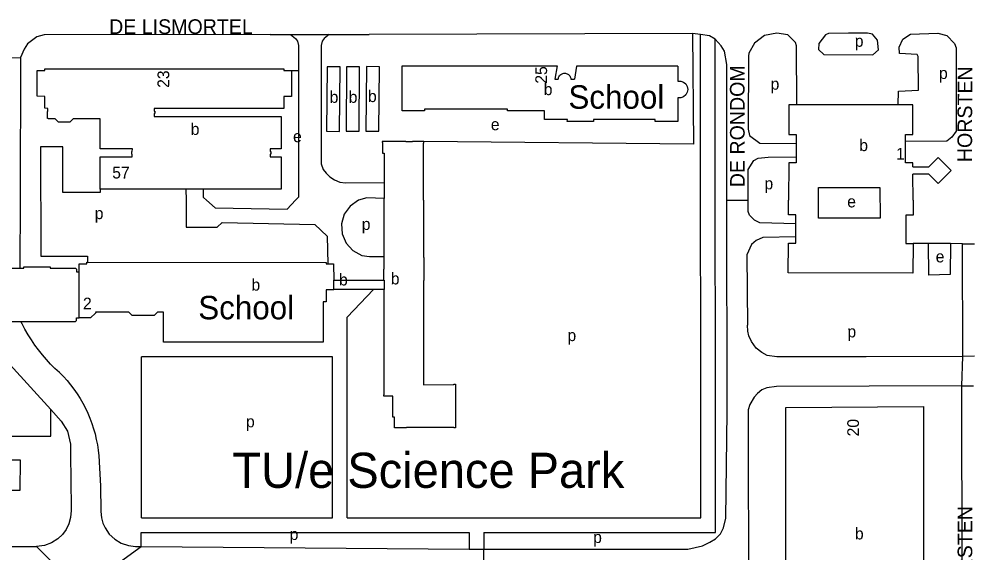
# Model space of a CAD drawing. Extents: x 161494 to 163033, y 383688 to 384862.
# Drawn here: x 162191.5 to 162517.1, y 384379.7 to 384561.8 of the extents above; entities that cross this region are included whole.
import ezdxf

# ---------------------------------------------------------------- set-up
doc = ezdxf.new("R2010")
doc.units = 0
for name, color, linetype in [('BLT_Basislijn', 7, 'Continuous'), ('BLT_Bebouwing', 7, 'Continuous'), ('BLT_Bebouwing_beschrifting', 7, 'Continuous'), ('BLT_Centroide', 7, 'Continuous'), ('BLT_Huisnummer', 7, 'Continuous'), ('BLT_Huisnummer_reeks', 7, 'Continuous'), ('BLT_Onderdoorgang_en_onderverdeling', 7, 'Continuous'), ('BLT_Onderverdeling_panden', 7, 'Continuous'), ('BLT_Sport_parknaam', 7, 'Continuous'), ('BLT_Straatnaam', 7, 'Continuous'), ('BLT_Vlakafsluiter', 7, 'Continuous')]:
    doc.layers.add(name, color=color, linetype=linetype)

msp = doc.modelspace()

# ---------------------------------------------------------------- linework, layer by layer
at = {"layer": 'BLT_Basislijn'}
for p, q in [((162277.25, 384556.55), (162284.21, 384556.56)), ((162284.21, 384556.56), (162291.93, 384556.57)), ((162291.93, 384556.57), (162297.41, 384556.57)), ((162297.41, 384556.57), (162311.03, 384556.59)), ((162421.44, 384556.93), (162311.03, 384556.59)), ((162424.11, 384556.57), (162421.44, 384556.93)), ((162424.22, 384391.71), (162424.11, 384556.57)), ((162429.23, 384386.71), (162429.11, 384555.03)), ((162284.55, 384544.31), (162286.93, 384544.24)), ((162286.93, 384544.24), (162286.93, 384501.09)), ((162248.5, 384503.76), (162248.51, 384500)), ((162286.93, 384501.09), (162285.92, 384500)), ((162191.85, 384500), (162191.79, 384476.84)), ((162258.48, 384497.41), (162255.56, 384500)), ((162285.92, 384500), (162283.04, 384496.92)), ((162258.48, 384497.41), (162283.04, 384496.92)), ((162260.8, 384492.37), (162292.53, 384491.73)), ((162292.53, 384491.73), (162296.74, 384487.8)), ((162296.74, 384487.8), (162296.91, 384478.32)), ((162513.58, 384485.17), (162517.59, 384485.2)), ((162303.54, 384391.71), (162303.54, 384460.12)), ((162233.3, 384391.71), (162233.3, 384446.58)), ((162298.54, 384391.71), (162298.54, 384446.55)), ((162517.68, 384446.82), (162513.64, 384446.73)), ((162188.54, 384443.92), (162202.39, 384428.59)), ((162513.36, 384436.68), (162517.26, 384436.66)), ((162513.52, 384355.52), (162513.36, 384436.68)), ((162350.2, 384391.71), (162424.22, 384391.71)), ((162233.21, 384381.92), (162233.17, 384386.71)), ((162350.2, 384386.71), (162429.23, 384386.71)), ((162127.04, 384381.9), (162197.47, 384381.94)), ((162233.21, 384381.92), (162345.2, 384381))]:
    msp.add_line(p, q, dxfattribs=at)
for points in [[(162277.25, 384556.55), (162200.08, 384556.42), (162197.64, 384555.73), (162194.42, 384553.41), (162193.24, 384551.6), (162191.97, 384548.7)], [(162284.21, 384556.56), (162285.91, 384555.21), (162286.61, 384554.27), (162286.93, 384552.82), (162286.93, 384544.24)], [(162297.41, 384556.57), (162295.7, 384555.21), (162295, 384554.27), (162294.67, 384552.82), (162294.67, 384512.49), (162295.34, 384510.54), (162296.33, 384509.26), (162297.6, 384508.03), (162299.2, 384507), (162301.03, 384506.24), (162302.96, 384505.97), (162316.16, 384506.06)], [(162421.44, 384556.93), (162421.79, 384519.13), (162329.71, 384520.04)], [(162429.11, 384555.03), (162427.14, 384556.15), (162424.11, 384556.57)], [(162457.04, 384532.57), (162456.89, 384552.68), (162456.58, 384553.79), (162453.97, 384556.49), (162450.15, 384556.97), (162445.98, 384556.21), (162442.58, 384553.63), (162440.67, 384550.23), (162440.48, 384549.23), (162440.36, 384524.31), (162440.83, 384522.15), (162444.39, 384519.47), (162456.75, 384519.33)], [(162474.63, 384556.98), (162467.77, 384556.94), (162466.82, 384556.43), (162464.52, 384553.47), (162464.37, 384551.5), (162466.27, 384549.77), (162482.91, 384549.62), (162484.88, 384551.34), (162484.56, 384554.59), (162482.81, 384556.65), (162481.14, 384557), (162474.63, 384556.98)], [(162491.59, 384532.57), (162491.76, 384537.21), (162498.52, 384537.53), (162498.38, 384549.07), (162498.11, 384549.78), (162492.04, 384550.13), (162491.92, 384552.2), (162493.15, 384555), (162495.79, 384556.7), (162505.17, 384557.05), (162508.16, 384556.18), (162510.8, 384553.47), (162511.43, 384552.04), (162511.43, 384523.64), (162509.96, 384521.5), (162508.26, 384520.17), (162494.14, 384520.08)], [(162433.15, 384500), (162433.12, 384546.37), (162432.31, 384550.83), (162431.16, 384552.66), (162429.11, 384555.03)], [(162191.97, 384548.7), (162191.85, 384500)], [(162219.25, 384503.76), (162219.25, 384502.68), (162206.47, 384502.68), (162206.46, 384518.29), (162198.88, 384518.28), (162198.99, 384480.93), (162214.88, 384480.93), (162214.9, 384478.86)], [(162440.4, 384500), (162440.39, 384510.51), (162442.33, 384513.56), (162443.76, 384514.39), (162447.27, 384514.72), (162456.75, 384514.87)], [(162255.56, 384500), (162254.48, 384500.95), (162254.48, 384503.76)], [(162316.16, 384500.57), (162310.19, 384500.88), (162307.36, 384500), (162304.53, 384498.05), (162302.48, 384495.28), (162301.63, 384491.95), (162301.76, 384488.51), (162303.13, 384485.36), (162305.47, 384482.82), (162308.5, 384481.21), (162311.16, 384480.85), (162316.17, 384480.8)], [(162248.51, 384500), (162248.53, 384490.85), (162259.19, 384490.85), (162260.8, 384492.37)], [(162433.2, 384427.7), (162433.15, 384500)], [(162456.64, 384492), (162444.33, 384492.3), (162442.52, 384493.27), (162440.83, 384494.95), (162440.4, 384496.16), (162440.4, 384500)], [(162456.63, 384487.55), (162445.43, 384487.33), (162443.12, 384486.24), (162441.53, 384484.94), (162439.99, 384481.37), (162440.17, 384457.38)], [(162501.89, 384485.28), (162496.67, 384485.22)], [(162509.43, 384485.25), (162509.32, 384474.63), (162502.05, 384474.44), (162501.89, 384485.28)], [(162509.43, 384485.25), (162501.89, 384485.28)], [(162513.58, 384485.17), (162509.43, 384485.25)], [(162513.64, 384446.73), (162513.58, 384485.17)], [(162312.55, 384469.57), (162303.54, 384460.12)], [(162205.33, 384441.23), (162203.78, 384442.66), (162202.29, 384444.14), (162200.85, 384445.68), (162199.48, 384447.28), (162198.16, 384448.93), (162196.91, 384450.62), (162195.72, 384452.36), (162194.6, 384454.15), (162193.55, 384455.98), (162192.57, 384457.84), (162192.18, 384458.64)], [(162513.64, 384446.73), (162480.72, 384446.63), (162450.17, 384446.55), (162446.93, 384447.01), (162445.01, 384448.02), (162443.12, 384449.56), (162441.53, 384451.77), (162440.66, 384453.71), (162440.27, 384455.38), (162440.17, 384457.38)], [(162298.54, 384446.55), (162233.3, 384446.58)], [(162205.33, 384441.23), (162206.66, 384439.89), (162207.93, 384438.49), (162209.14, 384437.04), (162210.28, 384435.54), (162211.36, 384433.99), (162212.38, 384432.4), (162213.32, 384430.77), (162214.2, 384429.1), (162215, 384427.39), (162215.73, 384425.65), (162216.39, 384423.88), (162216.97, 384422.08), (162217.48, 384420.27), (162217.9, 384418.43), (162218.25, 384416.57), (162218.52, 384414.71), (162218.71, 384412.83), (162218.82, 384410.94), (162218.83, 384410.7)], [(162513.36, 384436.68), (162450.09, 384436.43), (162446.77, 384436.05), (162445.01, 384435.32), (162443.54, 384434.13), (162442.46, 384432.84), (162440.96, 384430.36), (162440.4, 384428.46), (162440.34, 384425.23), (162440.51, 384363.61)], [(162121.02, 384419.5), (162202.39, 384419.51), (162202.39, 384428.59)], [(162202.39, 384428.59), (162205.94, 384424.66), (162208.03, 384421.25), (162209.1, 384416.8), (162209.1, 384409.79), (162209.2, 384407.98), (162209.21, 384406.16), (162209.19, 384405.28), (162209.34, 384394.14), (162209.14, 384391.74), (162208.53, 384389.57), (162207.62, 384387.72), (162206.31, 384385.95), (162204.76, 384384.5), (162202.6, 384383.15), (162200.19, 384382.28), (162197.47, 384381.94)], [(162350.2, 384381), (162418.98, 384380.95), (162419.84, 384380.99), (162424.82, 384382.11), (162427.33, 384383.31), (162429.21, 384384.54), (162430.9, 384386.23), (162431.97, 384388.21), (162432.76, 384391.57), (162433.2, 384427.7)], [(162218.83, 384410.7), (162219.36, 384402.56), (162219.4, 384393.87), (162219.63, 384391.67), (162220.14, 384389.87), (162220.89, 384388.2), (162222.33, 384386.1), (162224.18, 384384.34), (162226.43, 384382.98), (162228.93, 384382.19), (162231.24, 384381.92), (162233.21, 384381.92)], [(162233.3, 384391.71), (162298.54, 384391.71)], [(162303.54, 384391.71), (162350.2, 384391.71)], [(162233.17, 384386.71), (162345.2, 384386.71)], [(162345.2, 384386.71), (162345.2, 384381)], [(162350.2, 384386.71), (162350.2, 384381)], [(162345.2, 384381), (162350.2, 384381)]]:
    msp.add_lwpolyline(points, dxfattribs=at)
at = {"layer": 'BLT_Bebouwing'}
for p, q in [((162322.28, 384545.89), (162375.17, 384545.88)), ((162491.59, 384532.57), (162457.04, 384532.57)), ((162456.75, 384519.33), (162456.75, 384514.87)), ((162496.73, 384500), (162496.62, 384508.92)), ((162316.16, 384506.06), (162316.16, 384500.57)), ((162254.48, 384503.76), (162248.5, 384503.76)), ((162456.63, 384487.55), (162456.64, 384492)), ((162212.09, 384475.58), (162212.09, 384478.35)), ((162212.09, 384478.35), (162212.46, 384478.35)), ((162182.42, 384476.83), (162191.79, 384476.84)), ((162304.77, 384472.76), (162316.02, 384472.77)), ((162181.72, 384458.64), (162192.18, 384458.64))]:
    msp.add_line(p, q, dxfattribs=at)
for points in [[(162197.68, 384535.47), (162197.71, 384544.33), (162200.32, 384544.32), (162200.32, 384544.87), (162281.95, 384544.82), (162281.95, 384544.32), (162284.55, 384544.31)], [(162284.55, 384544.31), (162284.56, 384535.44), (162281.95, 384535.43), (162281.95, 384531.34), (162237.64, 384531.34), (162237.65, 384530.43), (162237.85, 384530.43), (162237.85, 384529.56), (162237.65, 384529.56), (162237.65, 384528.64), (162264.6, 384528.62), (162280.98, 384528.62), (162280.96, 384517.54), (162277.24, 384517.55), (162277.23, 384516.64), (162277.43, 384516.64), (162277.43, 384515.77), (162277.23, 384515.77), (162277.23, 384514.84), (162280.94, 384514.83), (162280.94, 384503.75), (162254.48, 384503.76)], [(162416.35, 384545.74), (162416.35, 384540.66), (162417.36, 384540.66), (162418.31, 384540.32), (162419.07, 384539.68), (162419.57, 384538.82), (162419.75, 384537.84), (162419.57, 384536.85), (162419.08, 384535.98), (162418.31, 384535.34), (162417.38, 384534.98), (162416.37, 384534.96), (162416.38, 384526.89), (162408.67, 384526.89), (162408.67, 384527.54), (162387.58, 384527.54), (162387.58, 384526.89), (162378.66, 384526.9), (162378.76, 384527.54), (162370.87, 384527.56), (162370.88, 384530.49), (162358.27, 384530.49), (162358.27, 384531.14), (162329.97, 384531.14), (162329.97, 384530.49), (162322.27, 384530.5), (162322.28, 384545.89)], [(162375.17, 384545.88), (162374.39, 384541.29), (162375.59, 384541.28), (162375.62, 384541.58), (162375.68, 384541.85), (162375.81, 384542.16), (162375.95, 384542.42), (162376.16, 384542.67), (162376.41, 384542.9), (162376.66, 384543.07), (162376.92, 384543.2), (162377.18, 384543.29), (162377.47, 384543.34), (162377.78, 384543.36), (162378.05, 384543.34), (162378.31, 384543.27), (162378.56, 384543.19), (162378.79, 384543.07), (162379.03, 384542.92), (162379.27, 384542.7), (162379.49, 384542.44), (162379.66, 384542.16), (162379.75, 384541.93), (162379.82, 384541.67), (162379.86, 384541.46), (162379.87, 384541.3), (162381.09, 384541.3)], [(162416.35, 384545.74), (162381.84, 384545.72), (162381.09, 384541.3)], [(162219.25, 384503.76), (162219.26, 384514.84), (162230.18, 384514.84), (162230.19, 384515.78), (162229.99, 384515.78), (162229.99, 384516.64), (162230.19, 384516.64), (162230.21, 384517.56), (162219.26, 384517.56), (162219.26, 384527.84), (162210.05, 384527.85), (162208.9, 384526.69), (162208.77, 384526.64), (162205.1, 384526.64), (162204.96, 384526.69), (162203.83, 384527.84), (162201.51, 384527.84), (162201.51, 384527.87), (162201.28, 384527.87), (162201.27, 384527.96), (162201.24, 384527.96), (162201.25, 384530.33), (162201.37, 384530.33), (162201.37, 384531.37), (162200.28, 384531.38), (162200.3, 384535.46), (162197.68, 384535.47)], [(162457.04, 384532.57), (162454.27, 384532.57), (162454.26, 384522.46), (162456.74, 384522.46), (162456.75, 384519.33)], [(162494.14, 384520.08), (162494.14, 384522.47), (162496.62, 384522.46), (162496.63, 384532.57), (162491.59, 384532.57)], [(162329.71, 384520.04), (162325.8, 384520.04), (162325.8, 384519.94), (162323.55, 384519.93), (162323.55, 384520.03), (162315.43, 384520.04), (162315.43, 384519.72), (162315.53, 384519.72), (162315.53, 384516.05), (162316.16, 384516.05), (162316.16, 384506.06)], [(162329.59, 384500), (162329.59, 384519.47), (162329.72, 384519.47), (162329.71, 384520.04)], [(162496.62, 384511.43), (162496.62, 384512.75), (162494.14, 384512.75), (162494.14, 384520.08)], [(162456.75, 384514.87), (162456.76, 384512.75), (162454.28, 384512.75), (162454.2, 384500)], [(162496.62, 384511.43), (162500, 384511.43), (162502.02, 384511.43), (162505.2, 384514.62), (162509.65, 384510.18), (162505.23, 384505.72), (162502.06, 384508.88), (162501.26, 384508.89), (162496.62, 384508.92)], [(162248.5, 384503.76), (162219.25, 384503.76)], [(162329.59, 384500), (162329.59, 384480.49), (162329.72, 384480.49), (162329.72, 384472.68), (162329.59, 384472.68), (162329.59, 384437.09), (162339.97, 384437.1), (162339.97, 384437.23), (162340.52, 384437.23), (162340.53, 384422.33), (162339.96, 384422.33), (162339.96, 384422.46), (162323.78, 384422.48), (162323.78, 384422.34), (162319.62, 384422.34), (162319.64, 384426.05), (162319.16, 384426.05), (162319.15, 384433.14), (162316.04, 384433.13), (162316.04, 384433.68), (162316.17, 384433.68), (162316.16, 384469.57)], [(162316.17, 384480.8), (162316.16, 384500.57)], [(162456.64, 384492), (162456.65, 384495.08), (162454.18, 384495.08), (162454.2, 384500)], [(162496.73, 384500), (162496.71, 384494.89), (162494.22, 384494.9), (162494.2, 384485.22), (162496.67, 384485.22)], [(162496.67, 384485.22), (162496.65, 384475.14), (162454.1, 384475.26), (162454.13, 384485.36), (162456.62, 384485.36), (162456.63, 384487.55)], [(162212.46, 384478.35), (162214.69, 384478.36), (162214.69, 384478.86), (162214.9, 384478.86)], [(162214.9, 384478.86), (162296.32, 384478.82), (162296.32, 384478.32), (162296.91, 384478.32)], [(162296.91, 384478.32), (162298.9, 384478.32), (162298.94, 384472.76), (162298.99, 384472.76)], [(162316.02, 384472.77), (162316.04, 384476.49), (162316.15, 384476.49), (162316.17, 384480.8)], [(162191.79, 384476.84), (162193.12, 384476.84), (162193.13, 384477.34), (162202.11, 384477.33), (162202.11, 384476.83), (162210.82, 384476.83), (162211.12, 384476.54), (162211.14, 384475.58), (162212.09, 384475.58)], [(162298.99, 384472.76), (162304.77, 384472.76)], [(162299, 384469.59), (162298.93, 384469.59), (162298.93, 384469.44), (162296.33, 384469.44), (162296.31, 384465.34), (162295.36, 384465.35)], [(162304.75, 384469.58), (162299, 384469.59)], [(162312.55, 384469.57), (162304.75, 384469.58)], [(162316.16, 384469.57), (162312.55, 384469.57)], [(162295.36, 384465.35), (162295.34, 384451.55), (162240.84, 384451.58), (162240.84, 384461.86), (162238.81, 384461.85), (162237.66, 384460.71), (162237.54, 384460.65), (162230.27, 384460.65), (162230.15, 384460.71), (162229, 384461.85), (162217.63, 384461.87), (162217.68, 384461.58), (162217.62, 384461.45), (162215.96, 384459.85), (162212.07, 384459.86)], [(162192.18, 384458.64), (162210.81, 384458.64), (162211.12, 384458.94)], [(162211.12, 384458.94), (162211.12, 384459.86), (162212.07, 384459.86)], [(162453.23, 384343.09), (162453.29, 384429.34), (162500.19, 384429.6), (162500.18, 384324.01)], [(162181.45, 384411.45), (162191.85, 384411.43), (162191.82, 384401), (162181.42, 384401.02)]]:
    msp.add_lwpolyline(points, dxfattribs=at)
for points in [[(162296.7, 384545.55), (162296.49, 384523.55), (162300.93, 384523.51), (162301.13, 384545.51)], [(162303.34, 384545.57), (162303.14, 384523.57), (162307.57, 384523.53), (162307.78, 384545.54)], [(162310.07, 384545.6), (162309.86, 384523.59), (162314.29, 384523.56), (162314.5, 384545.57)], [(162464.45, 384493.86), (162464.35, 384504.31), (162485.31, 384504.35), (162485.42, 384493.9)]]:
    msp.add_lwpolyline(points, close=True, dxfattribs=at)
at = {"layer": 'BLT_Onderdoorgang_en_onderverdeling'}
msp.add_lwpolyline([(162316.02, 384472.77), (162316.17, 384472.77), (162316.16, 384469.57)], dxfattribs=at)
at = {"layer": 'BLT_Onderverdeling_panden'}
for p, q in [((162212.07, 384459.86), (162212.09, 384475.58)), ((162299, 384469.59), (162298.99, 384472.76))]:
    msp.add_line(p, q, dxfattribs=at)
at = {"layer": 'BLT_Vlakafsluiter'}
for p, q in [((162181.47, 384548.49), (162191.97, 384548.7)), ((162433.15, 384500), (162440.4, 384500)), ((162513.36, 384436.68), (162513.64, 384446.73)), ((162197.47, 384381.94), (162208.56, 384370.74)), ((162217.82, 384370.78), (162233.21, 384381.92)), ((162350.2, 384371.34), (162350.2, 384381))]:
    msp.add_line(p, q, dxfattribs=at)

# ---------------------------------------------------------------- texts
at = {"layer": 'BLT_Bebouwing_beschrifting'}
for p in [(162379.05, 384531.24), (162252.7, 384459.39)]:
    msp.add_text('School', height=8, dxfattribs=at).set_placement(p)
at = {"layer": 'BLT_Centroide'}
for s, p in [('p', (162476.79, 384552.37)), ('p', (162505.53, 384541.39)), ('b', (162370.62, 384535.88)), ('p', (162448.05, 384537.73)), ('b', (162297.53, 384533.25)), ('b', (162304.04, 384533.25)), ('b', (162310.62, 384533.51)), ('e', (162352.57, 384523.91)), ('b', (162250.12, 384522.31)), ('e', (162285.05, 384519.83)), ('b', (162478.32, 384516.78)), ('p', (162445.96, 384503.75)), ('e', (162474.21, 384497.58)), ('p', (162217.36, 384493.58)), ('p', (162308.5, 384489.89)), ('e', (162504.4, 384478.82)), ('b', (162300.75, 384470.94)), ('b', (162318.41, 384471.3)), ('b', (162270.85, 384469.19)), ('p', (162474.28, 384453.23)), ('p', (162378.72, 384451.95)), ('p', (162268.99, 384422.54)), ('p', (162283.89, 384384.1)), ('b', (162476.84, 384384.29)), ('p', (162387.48, 384383.08))]:
    msp.add_text(s, height=4, dxfattribs=at).set_placement(p)
at = {"layer": 'BLT_Huisnummer'}
for s, rotation, p in [('25', 89.6507, (162371.73, 384539.77)), ('1', 0.0033, (162490.86, 384513.89)), ('2', 359.77, (162213.33, 384462.79)), ('20', 90.021, (162478.22, 384419.45))]:
    msp.add_text(s, height=4, rotation=rotation, dxfattribs=at).set_placement(p)
at = {"layer": 'BLT_Huisnummer_reeks'}
for s, rotation, p in [('23', 89.77, (162242.76, 384538.35)), ('57', 359.77, (162223.32, 384507.45))]:
    msp.add_text(s, height=4, rotation=rotation, dxfattribs=at).set_placement(p)
at = {"layer": 'BLT_Sport_parknaam'}
msp.add_text('TU/e Science Park', height=12, dxfattribs=at).set_placement((162264.35, 384401.89))
at = {"layer": 'BLT_Straatnaam'}
for s, rotation, p in [('DE LISMORTEL', 0.0477, (162222.27, 384556.73)), ('DE RONDOM', 90.0852, (162439.22, 384504.46)), ('HORSTEN', 89.8991, (162516.82, 384513.01)), ('HORSTEN', 89.8991, (162516.86, 384363))]:
    msp.add_text(s, height=5, rotation=rotation, dxfattribs=at).set_placement(p)

doc.saveas('drawing.dxf')
